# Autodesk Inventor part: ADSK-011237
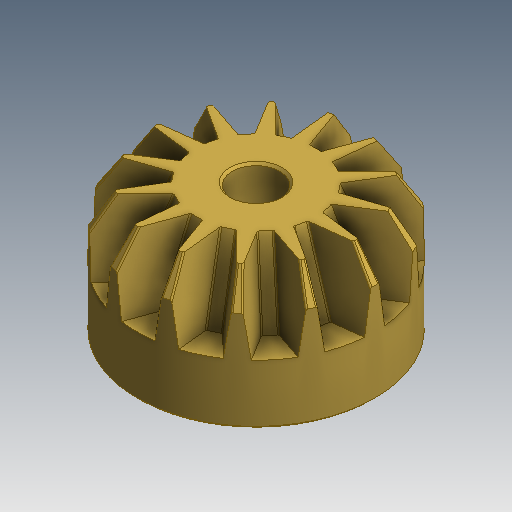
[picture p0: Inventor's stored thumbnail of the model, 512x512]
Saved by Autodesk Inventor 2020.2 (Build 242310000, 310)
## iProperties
Created: 2000-10
Part Number: ADSK-011237
Document SubType Name: Modeling
Designer: wymerj
Material: Générique
Density: 1 g/cm^3
Appearance: Vorgabe
Mass: 70.8958 g
Surface Area: 158.538 cm^2
Volume: 70.8958 cm^3
Control State: 0
Master: False
Checked Out: False
Shininess: 0.0
Length Units: 11269
Angle Units: 11279
Time Units: 11290
Mass Units: 11283
Length Display Precision: 3
Angle Display Precision: 2
Compacted: True
Dimensions: 33,7x61x61 mm
Mass: 0,071 kg
VLT_Material: Generic
Density: 0.0
Volumn: 0.0
Area: 0.0
PropertySet Name: Model Information
Author: wymerj
Revision Number: -
Title: ADSK-011237
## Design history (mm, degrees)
derived "ADSK-011848.ipt"
  workplane "Work Plane1"
  workplane "Work Plane2"
  workaxis "Work Axis1"
node "Solide1"
node "Corps solides"
node "Corps surfaciques"
node "FonctionRepérage2"
sketch "Sketch2"
  geometry: 7 further points; 6 other entities
  constraints: 3 horizontal alignment, 1 vertical alignment, 3 other
sketch "Sketch3"
  geometry: C1 r 30.48 at (0, 0) reference; C2 r 6.096 at (0, 0) reference
feature "DerivedBody::ADSK-011848.ipt"
